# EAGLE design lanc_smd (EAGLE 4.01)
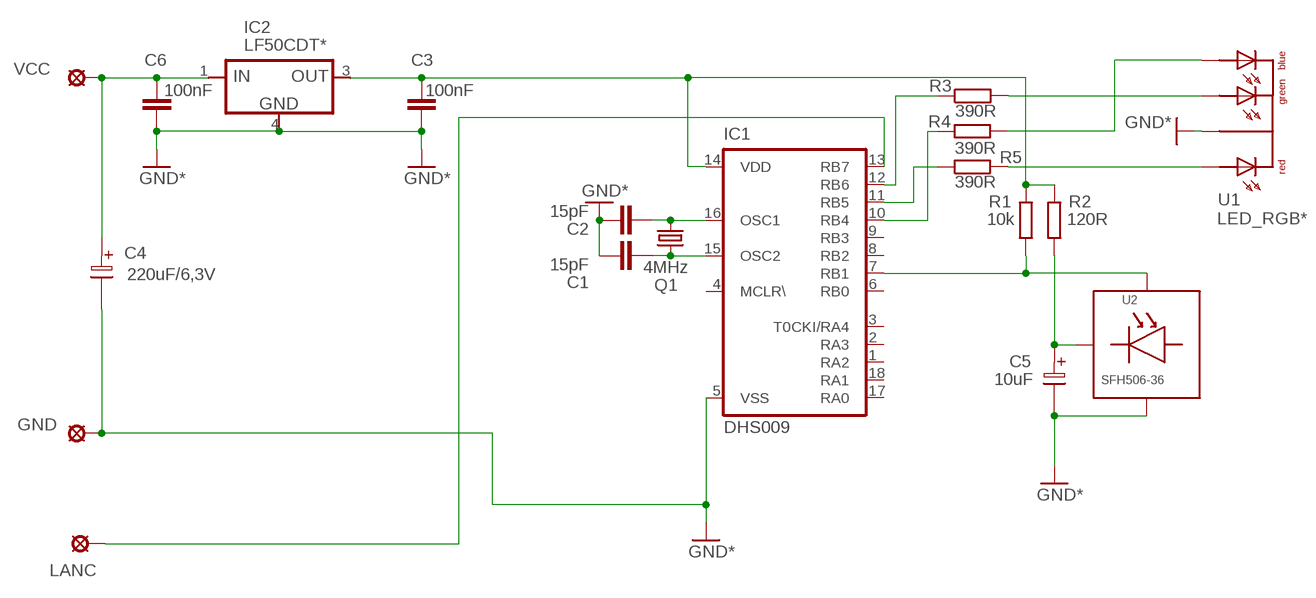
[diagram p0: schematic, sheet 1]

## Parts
C1  15pF  C-EUC1206  [C1206]
C2  15pF  C-EUC1206  [C1206]
C3  100nF  C-EUC1206  [C1206]
C4  220uF/6,3V  E5X11  [E50]
C5  10uF  CTSB  [CTSB]
C6  100nF  C-EUC1206  [C1206]
GND  GND  LSP10  [LSP10]
IC1  DHS009  PIC16F83SO  [SO-18W]
IC2  LF50CDT*  [DPAK]
LANC  LANC  LSP10  [LSP10]
Q1  4MHz  HC49U-V  [HC49U-V]
R1  10k  R-EU_M1206  [M1206]
R2  120R  R-EU_M1206  [M1206]
R3  390R  R-EU_M1206  [M1206]
R4  390R  R-EU_M1206  [M1206]
R5  390R  R-EU_M1206  [M1206]
U1  LED_RGB*  [LED_5MM_RGB]
U2  SFH506-36  [SFH506]
VCC  LSP10  [LSP10]

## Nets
GND: C1.2 C2.2 C3.1 C4.2 C5.2 C6.1 GND.MP IC1.5(VSS) IC2.4(GND) U1.C U2.3 ; supply symbol labelled GND*
N$1: C1.1 IC1.15(OSC2) Q1.2
N$2: C2.1 IC1.16(OSC1) Q1.1
N$3: IC1.13(RB7) LANC.MP
N$4: IC1.10(RB4) R4.1
N$5: C4.1 C6.2 IC2.1(IN) VCC.MP
N$6: IC1.11(RB5) R5.1
N$7: IC1.12(RB6) R3.1
N$8: C5.1 R2.2 U2.2
N$9: R4.2 U1.AB
N$10: IC1.7(RB1) R1.2 U2.1
N$11: R5.2 U1.AR
N$12: R3.2 U1.AG
N$17: C3.2 IC1.14(VDD) IC2.3(OUT) R1.1 R2.1
Unconnected: IC1.1(RA2) IC1.2(RA3) IC1.3(T0CKI/RA4) IC1.4(MCLR\) IC1.6(RB0) IC1.8(RB2) IC1.9(RB3) IC1.17(RA0) IC1.18(RA1)

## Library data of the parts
C1-C3 C6 = rcl:C-EU: CAPACITOR, European symbol
C4 = GM99:E5X11
C5 = GM99:CTSB
GND LANC VCC = solpad:LSP10: SOLDER PAD
IC1 = microchip:PIC16F8*: MICROCONTROLLER 8-Bit PIC16F8X Family - CMOS Flash/EEPROM Pin Compatible : PIC16F83, PIC16CR83, PIC16F84A, PIC16CR84 see also PIC16C*
IC2 = DH_servis:LF50CDT
Q1 = crystal:HC49U-V: CRYSTAL
R1-R5 = rcl:R-EU_: RESISTOR, European symbol
U1 = DH_servis:LED_RGB
U2 = GM99:SFH506-36

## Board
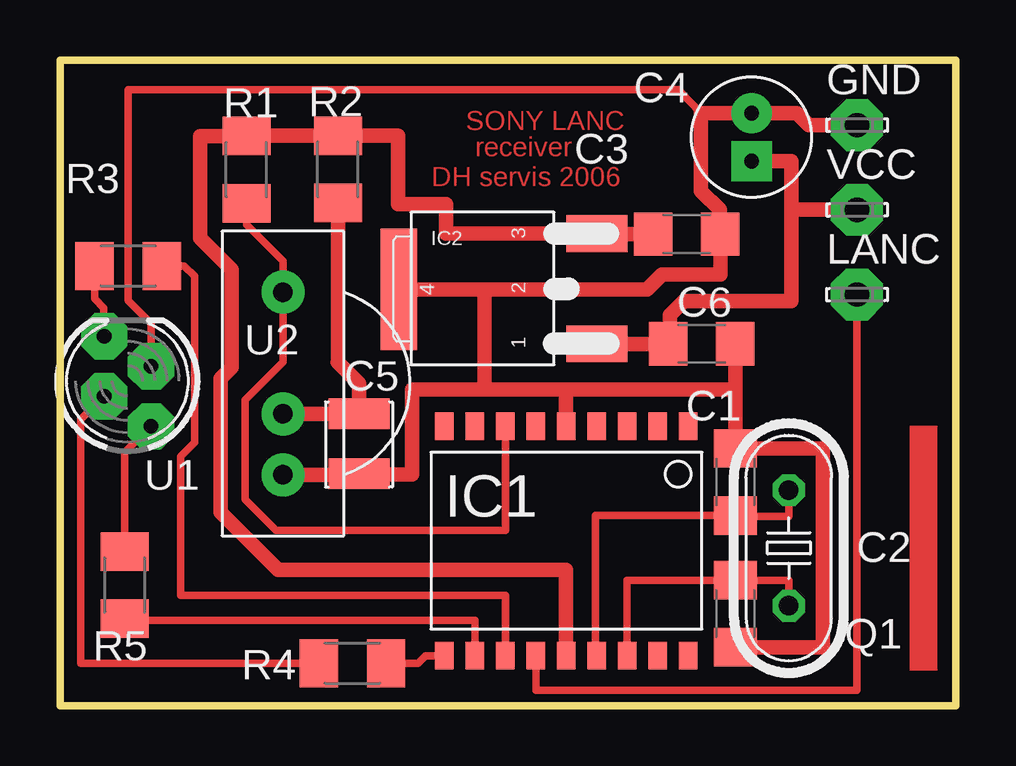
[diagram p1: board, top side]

Size 37.34 x 26.92 mm. Coordinates in mm from the lower left corner, seen from the top.
Outline: 0,0 37.34,0 37.34,26.92 0,26.92 0,0
Copper layers used: Top

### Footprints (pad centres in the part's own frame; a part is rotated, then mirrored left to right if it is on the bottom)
C1206 = smd 1.6 x 1.8: 1 -1.4,0; 2 1.4,0
E50 = drill 0.61 pad 1.676 square: 1 0,0 | drill 0.61 pad 1.676 round: 2 2,0
CTSB = smd 1.27 x 2.54: 1 -1.252,0; 2 1.247,0
LSP10 = drill 1.016 pad 2.159 octagon: MP 0,0
SO-18W = smd 0.762 x 1.143: 1 -5.08,-4.788; 2 -3.81,-4.788; 3 -2.54,-4.788; 4 -1.27,-4.788; 5 0,-4.788; 6 1.27,-4.788; 7 2.54,-4.788; 8 3.81,-4.788; 9 5.08,-4.788; 10 5.08,4.788; 11 3.81,4.788; 12 2.54,4.788; 13 1.27,4.788; 14 0,4.788; 15 -1.27,4.788; 16 -2.54,4.788; 17 -3.81,4.788; 18 -5.08,4.788
DPAK = smd 1.524 x 2.54: 1 0.94,-1.702; 3 5.537,-1.702 | smd 5.08 x 1.524: 4 3.215,6.559
HC49U-V = drill 0.813 octagon: 1 -2.413,0; 2 2.413,0
M1206 = smd 1.6 x 2: 1 -1.4,0; 2 1.4,0
LED_5MM_RGB = drill 0.61 pad 1.93 octagon: AB -0.635,0.978; AG 1.867,0.978; AR -1.892,-0.978; C 0.61,-0.978
SFH506 = drill 0.813 pad 1.778 round: 1 0,7.62; 2 0,2.54; 3 0,0

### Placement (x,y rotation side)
C1  28.16,9.33 90 top
C2  28.15,3.84 270 top
C3  26.12,19.67 180 top
C4  28.83,22.71 90 top
C5  12.47,10.92 270 top
C6  26.75,15.09 180 top
GND  33.22,24.21 0 top
IC1  21.1,6.87 180 top
IC2  20.68,14.15 90 top
LANC  33.22,17.14 0 top
Q1  30.38,6.58 90 top
R1  7.77,22.35 270 top
R2  11.59,22.36 270 top
R3  2.84,18.34 180 top
R4  12.19,1.78 180 top
R5  2.69,5.03 90 top
U1  2.82,13.54 90 top
U2  9.3,9.62 0 top
VCC  33.22,20.68 0 top

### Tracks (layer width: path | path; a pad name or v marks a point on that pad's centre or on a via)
GND
  Top 0.305: C2.2 28.15,2.46 | 17.3,17.35 17.7,17.35 | 14.15,17.32 14.17,17.32 | 14.15,17.35 14.15,17.32 | IC2.4 14.12,17.32 14.15,17.32 | U1.C 3.8,15.94 2.85,16.89 2.85,25.68 25.78,25.68 26.72,24.71
  Top 0.406: 26.72,24.71
  Top 0.61: 28.15,13.18 C6.1 | 17.7,17.35 17.7,13.18 17.83,13.18 | 14.15,17.35 17.3,17.35 24.46,17.35 25.09,17.98 27.52,17.98 C3.1 27.52,19.72 27.48,19.76 27.51,19.79 27.51,20.68 26.72,21.46 26.72,24.71 C4.2 30.71,24.71 31.22,24.21 GND.MP | 17.83,13.18 18.47,13.18 | 22.07,13.18 28.15,13.18 | 17.83,13.18 14.68,13.18 14.68,9.65 12.72,9.65 | 12.72,9.65 12.8,9.65 | 17.83,13.18 22.07,13.18 | IC1.5 21.1,13.18 22.07,13.18 | 28.15,10.74 28.16,10.74 C1.2 31.8,10.73 31.8,2.44 C2.2 | 28.15,13.18 28.15,10.74 | 28.15,10.74 28.14,10.74 | C2.2 | C2.2 | 12.65,9.67 12.65,9.65 12.72,9.65 | 12.65,9.67 C5.2 12.45,9.67 12.45,9.62 | 12.65,9.67 12.65,9.68 | 12.45,9.62 U2.3 | 12.45,9.62 12.45,9.6
N$1
  Top 0.305: 28.16,7.9 28.12,7.9 | 28.16,7.9 C1.1 22.33,7.93 22.33,1.88 | Q1.2 30.38,7.9 28.16,7.9 | 22.33,1.88 22.33,1.85 | IC1.15 22.33,1.88
N$2
  Top 0.305: C2.1 | IC1.16 23.64,5.23 C2.1 | Q1.1 30.38,5.23 C2.1
N$3
  Top 0.305: LANC.MP 33.22,0.64 19.84,0.64 IC1.13
N$4
  Top 0.305: 15.24,2.08 IC1.10 | 15.24,2.08 | 15.24,2.08 14.94,1.78 R4.1
N$5
  Top 0.305: 25.38,15.09 C6.2 25.43,15.09
  Top 0.61: IC2.1 C6.2 | C4.1 30.48,22.71 30.48,20.17 | 30.48,20.17 30.48,16.87 26.01,16.87 25.43,16.28 25.43,15.09 | VCC.MP 30.48,20.68 30.48,20.17
N$6
  Top 0.305: IC1.11 17.29,3.56 2.69,3.56 R5.1
N$7
  Top 0.305: IC1.12 18.56,4.6 5.03,4.6 5.03,10.39 5.61,10.97 5.61,17.91 5.18,18.34 R3.1
N$8
  Top 0.61: 12.39,12.17 12.39,12.19 | 12.39,12.17 C5.1 | U2.2 12.39,12.16 12.39,12.17 | C5.1 10.62,12.17 | C5.1 12.47,13.44 11.68,14.22 | 11.68,14.22 11.58,14.33 | R2.2 11.59,14.32 11.68,14.22
N$9
  Top 0.305: U1.AB 1.83,12.9 0.86,11.94 0.86,1.78 R4.2
N$10
  Top 0.305: IC1.7 18.56,7.32 17.68,7.32 | 7.77,20.9 R1.2 | 7.77,20.9 7.78,20.9 | 17.68,7.32 17.65,7.32 | 17.68,7.32 9.02,7.32 7.72,8.61 7.72,12.75 9.3,14.33 9.3,14.63 9.3,17.22 | 9.3,17.22 U2.1 | U2.1 | 7.77,20.9 7.77,20.07 9.3,18.54 U2.1 | 9.3,17.22 9.3,17.2
N$11
  Top 0.305: U1.AR 3.79,11.66 2.69,10.57 R5.2
N$12
  Top 0.305: R3.2 1.45,16.97 1.83,16.59 1.83,15.39 U1.AG
N$17
  Top 0.61: C3.2 22.38,19.67 IC2.3 16.1,19.68 16.1,20.9 14.1,20.9 14.1,23.76 R2.1 8.05,23.76 | IC1.14 21.1,5.66 9.09,5.66 6.71,8.05 6.71,13.64 7.16,14.1 7.16,18.19 5.84,19.51 5.84,23.75 R1.1 8.05,23.75 8.05,23.76 | 8.05,23.76 8.05,23.77
(copper drawn outside any net)
  shapes: Top area x1

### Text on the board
Top: SONY LANC | receiver | DH servis 2006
